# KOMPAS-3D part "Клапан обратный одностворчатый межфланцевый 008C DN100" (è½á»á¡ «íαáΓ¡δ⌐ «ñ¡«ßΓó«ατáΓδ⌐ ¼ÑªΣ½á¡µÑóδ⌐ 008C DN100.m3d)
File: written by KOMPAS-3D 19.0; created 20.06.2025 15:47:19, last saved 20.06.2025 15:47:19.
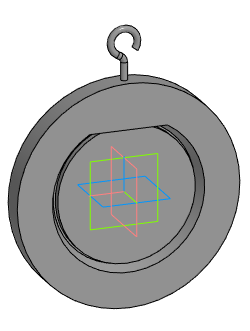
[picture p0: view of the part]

Document properties: Полное имя файла: E:\Dendor Работа Сачек\3D для проектировщиков\5.1 Тип 008C. Клапан обратный одностворчатый межфланцевый\stp_Клапан обратный одностворчатый межфланцевый 008C\Клапан обратный одностворчатый межфланцевый 008C DN100.m3d

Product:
- Part/product: Клапан обратный одностворчатый межфланцевый 008C DN100

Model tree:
1. Операция без истории:1  (labels: Клапан обратный одностворчатый межфланцевый 008C DN100)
